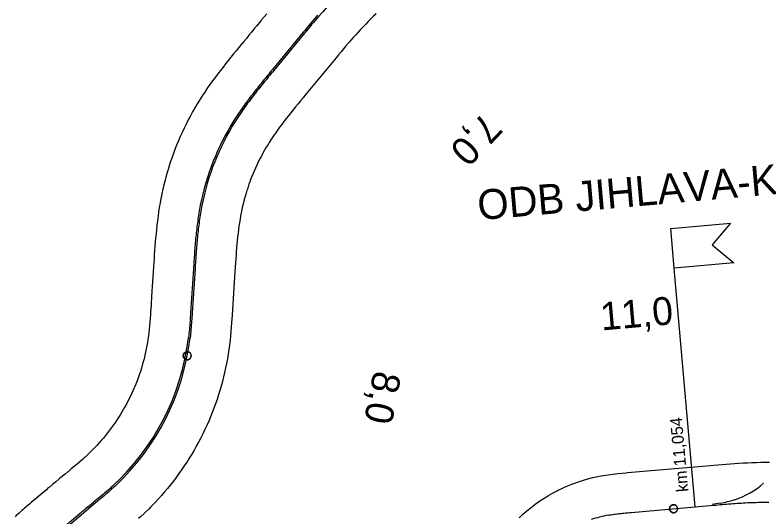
# Model space of a CAD drawing. Extents: x -670810 to -649614, y -1131928 to -1115069.
# Drawn here: x -670180 to -668294, y -1128491 to -1127234 of the extents above; entities that cross this region are included whole.
import ezdxf

# ---------------------------------------------------------------- set-up
doc = ezdxf.new("R2010")
doc.units = 0
for name, color, linetype in [('519 Var SK-4 Praporky stanic', 7, 'Continuous'), ('hranice_VRT_ZUR_Vysocina', 7, 'Continuous'), ('Osa koleje', 7, 'Continuous'), ('Osa koleje úprava GPK', 7, 'Continuous'), ('Situace - Osa koleje 2D', 7, 'Continuous'), ('Staničení - hlavní staničení + kolečka 1k', 7, 'Continuous')]:
    doc.layers.add(name, color=color, linetype=linetype)

# ---------------------------------------------------------------- blocks, each defined once
blk = doc.blocks.new('Sit10Kruh_175')
at = {"layer": 'Staničení - hlavní staničení + kolečka 1k'}
blk.add_lwpolyline([(10, 0), (10, 0.6), (9.9, 1.3), (9.8, 1.9), (9.7, 2.5), (9.5, 3.1), (9.3, 3.7), (9, 4.3), (8.8, 4.8), (8.4, 5.4), (8.1, 5.9), (7.7, 6.4), (7.3, 6.8), (6.8, 7.3), (6.4, 7.7), (5.9, 8.1), (5.4, 8.4), (4.8, 8.8), (4.3, 9), (3.7, 9.3), (3.1, 9.5), (2.5, 9.7), (1.9, 9.8), (1.3, 9.9), (0.6, 10), (0, 10), (-0.6, 10), (-1.3, 9.9), (-1.9, 9.8), (-2.5, 9.7), (-3.1, 9.5), (-3.7, 9.3), (-4.3, 9), (-4.8, 8.8), (-5.4, 8.4), (-5.9, 8.1), (-6.4, 7.7), (-6.8, 7.3), (-7.3, 6.8), (-7.7, 6.4), (-8.1, 5.9), (-8.4, 5.4), (-8.8, 4.8), (-9, 4.3), (-9.3, 3.7), (-9.5, 3.1), (-9.7, 2.5), (-9.8, 1.9), (-9.9, 1.3), (-10, 0.6), (-10, 0), (-10, -0.6), (-9.9, -1.3), (-9.8, -1.9), (-9.7, -2.5), (-9.5, -3.1), (-9.3, -3.7), (-9, -4.3), (-8.8, -4.8), (-8.4, -5.4), (-8.1, -5.9), (-7.7, -6.4), (-7.3, -6.8), (-6.8, -7.3), (-6.4, -7.7), (-5.9, -8.1), (-5.4, -8.4), (-4.8, -8.8), (-4.3, -9), (-3.7, -9.3), (-3.1, -9.5), (-2.5, -9.7), (-1.9, -9.8), (-1.3, -9.9), (-0.6, -10), (0, -10), (0.6, -10), (1.3, -9.9), (1.9, -9.8), (2.5, -9.7), (3.1, -9.5), (3.7, -9.3), (4.3, -9), (4.8, -8.8), (5.4, -8.4), (5.9, -8.1), (6.4, -7.7), (6.8, -7.3), (7.3, -6.8), (7.7, -6.4), (8.1, -5.9), (8.4, -5.4), (8.8, -4.8), (9, -4.3), (9.3, -3.7), (9.5, -3.1), (9.7, -2.5), (9.8, -1.9), (9.9, -1.3)], close=True, dxfattribs=at)
blk.add_circle((0, 0), 10, dxfattribs=at)
blk = doc.blocks.new('Sit10Kruh_177')
at = {"layer": 'Staničení - hlavní staničení + kolečka 1k'}
blk.add_lwpolyline([(10, 0), (10, 0.6), (9.9, 1.3), (9.8, 1.9), (9.7, 2.5), (9.5, 3.1), (9.3, 3.7), (9, 4.3), (8.8, 4.8), (8.4, 5.4), (8.1, 5.9), (7.7, 6.4), (7.3, 6.8), (6.8, 7.3), (6.4, 7.7), (5.9, 8.1), (5.4, 8.4), (4.8, 8.8), (4.3, 9), (3.7, 9.3), (3.1, 9.5), (2.5, 9.7), (1.9, 9.8), (1.3, 9.9), (0.6, 10), (0, 10), (-0.6, 10), (-1.3, 9.9), (-1.9, 9.8), (-2.5, 9.7), (-3.1, 9.5), (-3.7, 9.3), (-4.3, 9), (-4.8, 8.8), (-5.4, 8.4), (-5.9, 8.1), (-6.4, 7.7), (-6.8, 7.3), (-7.3, 6.8), (-7.7, 6.4), (-8.1, 5.9), (-8.4, 5.4), (-8.8, 4.8), (-9, 4.3), (-9.3, 3.7), (-9.5, 3.1), (-9.7, 2.5), (-9.8, 1.9), (-9.9, 1.3), (-10, 0.6), (-10, 0), (-10, -0.6), (-9.9, -1.3), (-9.8, -1.9), (-9.7, -2.5), (-9.5, -3.1), (-9.3, -3.7), (-9, -4.3), (-8.8, -4.8), (-8.4, -5.4), (-8.1, -5.9), (-7.7, -6.4), (-7.3, -6.8), (-6.8, -7.3), (-6.4, -7.7), (-5.9, -8.1), (-5.4, -8.4), (-4.8, -8.8), (-4.3, -9), (-3.7, -9.3), (-3.1, -9.5), (-2.5, -9.7), (-1.9, -9.8), (-1.3, -9.9), (-0.6, -10), (0, -10), (0.6, -10), (1.3, -9.9), (1.9, -9.8), (2.5, -9.7), (3.1, -9.5), (3.7, -9.3), (4.3, -9), (4.8, -8.8), (5.4, -8.4), (5.9, -8.1), (6.4, -7.7), (6.8, -7.3), (7.3, -6.8), (7.7, -6.4), (8.1, -5.9), (8.4, -5.4), (8.8, -4.8), (9, -4.3), (9.3, -3.7), (9.5, -3.1), (9.7, -2.5), (9.8, -1.9), (9.9, -1.3)], close=True, dxfattribs=at)
blk.add_circle((0, 0), 10, dxfattribs=at)
blk = doc.blocks.new('_U709')
at = {"layer": '519 Var SK-4 Praporky stanic'}
blk.add_line((73.8, -456.3), (21.4, 141.2), dxfattribs=at)
blk.add_lwpolyline([(12.7, 240.8), (162.1, 253.9), (116.7, 199.7), (170.8, 154.3), (21.4, 141.2)], close=True, dxfattribs=at)
for s, height, rotation, p in [('ODB JIHLAVA-KALVÁRIE', 75, 5.0106, (-467.5, 261.5)), ('km 11,054', 30, 95.0106, (56.9, -417.8))]:
    blk.add_text(s, height=height, rotation=rotation, dxfattribs=at).set_placement(p)

msp = doc.modelspace()

# ---------------------------------------------------------------- linework, layer by layer
at = {"layer": 'hranice_VRT_ZUR_Vysocina'}
for points in [[(-669550.4, -1127230.9), (-669556.8, -1127238.6), (-669563.1, -1127246.3), (-669564.2, -1127247.5), (-669569.5, -1127254), (-669575.9, -1127261.7), (-669579.8, -1127266.5), (-669582.2, -1127269.4), (-669588.6, -1127277.1), (-669594.9, -1127284.8), (-669601.3, -1127292.6), (-669607.7, -1127300.3), (-669612.9, -1127306.6), (-669614, -1127308), (-669620.5, -1127315.8), (-669626.9, -1127323.6), (-669633.4, -1127331.6), (-669640, -1127339.6), (-669646.5, -1127347.8), (-669653.1, -1127356), (-669659.7, -1127364.4), (-669666.3, -1127372.9), (-669672.9, -1127381.5), (-669679.5, -1127390.3), (-669686.1, -1127399.2), (-669692.6, -1127408.3), (-669699, -1127417.5), (-669705.4, -1127426.9), (-669711.7, -1127436.5), (-669716.9, -1127444.7), (-669718.1, -1127446.5), (-669724, -1127456.1), (-669729.9, -1127466.1), (-669735.7, -1127476.2), (-669741.3, -1127486.4), (-669746.7, -1127496.6), (-669751.9, -1127507), (-669757, -1127517.4), (-669762, -1127527.9), (-669766.7, -1127538.4), (-669770.4, -1127547), (-669771.5, -1127549.4), (-669775.8, -1127559.8), (-669780, -1127570.6), (-669784, -1127581.2), (-669785.3, -1127585), (-669787.9, -1127592.3), (-669789.3, -1127596.4), (-669791.7, -1127603.5), (-669795.2, -1127614.2), (-669796.5, -1127618.5), (-669798.7, -1127625.7), (-669801.8, -1127636.7), (-669804.8, -1127647.9), (-669807.7, -1127659.2), (-669810.3, -1127670.5), (-669812.8, -1127681.7), (-669814.6, -1127690.9), (-669815.1, -1127693.5), (-669817.2, -1127704.5), (-669819.1, -1127715.8), (-669820.8, -1127727), (-669822.4, -1127738.1), (-669823.8, -1127749.1), (-669825.2, -1127760.1), (-669826.3, -1127771), (-669827.4, -1127781.8), (-669828.4, -1127792.4), (-669829.3, -1127803), (-669830.1, -1127813.5), (-669830.9, -1127823.9), (-669831.7, -1127834.3), (-669832.3, -1127844.5), (-669833, -1127854.6), (-669833.6, -1127863.3)], [(-669276.8, -1127230.8), (-669283.4, -1127237.2), (-669289.9, -1127243.7), (-669296.3, -1127250.2), (-669302.7, -1127256.8), (-669309.1, -1127263.4), (-669315.4, -1127270.1), (-669321.6, -1127276.8), (-669327.8, -1127283.6), (-669333.9, -1127290.4), (-669340, -1127297.3), (-669344.3, -1127302.2), (-669345.9, -1127304.1), (-669352.1, -1127311.3), (-669358.1, -1127318.5), (-669364.3, -1127325.9), (-669370.5, -1127333.4), (-669376.8, -1127341), (-669455.7, -1127436.6), (-669459.5, -1127441.2), (-669465.8, -1127448.9), (-669472, -1127456.4), (-669478.1, -1127463.9), (-669484.2, -1127471.4), (-669490.1, -1127478.8), (-669495.9, -1127486.1), (-669501.7, -1127493.4), (-669507.3, -1127500.7), (-669512.8, -1127507.9), (-669518.1, -1127515.1), (-669523.3, -1127522.3), (-669528.4, -1127529.5), (-669533.3, -1127536.6), (-669538.1, -1127543.8), (-669542.8, -1127551.1), (-669544.5, -1127553.7), (-669547.1, -1127557.9), (-669551.5, -1127565.2), (-669555.7, -1127572.5), (-669559.8, -1127579.8), (-669563.8, -1127587.1), (-669567.7, -1127594.6), (-669571.4, -1127602.1), (-669575, -1127609.7), (-669578.5, -1127617.3), (-669581.8, -1127624.8), (-669585.2, -1127632.7), (-669588.3, -1127640.5), (-669591.4, -1127648.5), (-669592.5, -1127651.7), (-669594.2, -1127656.3), (-669594.8, -1127658), (-669596.9, -1127664), (-669599.6, -1127672.4), (-669600.1, -1127673.9), (-669602, -1127680), (-669604.4, -1127688.1), (-669606.6, -1127696.2), (-669608.7, -1127704.3), (-669610.7, -1127712.5), (-669612.5, -1127720.7), (-669614.3, -1127729.2), (-669614.4, -1127729.8), (-669615.8, -1127737.1), (-669617.2, -1127745.6), (-669618.6, -1127754.1), (-669619.9, -1127762.7), (-669621, -1127771.5), (-669622.1, -1127780.3), (-669623.1, -1127789.3), (-669624.1, -1127798.4), (-669624.9, -1127807.6), (-669625.8, -1127816.9), (-669626.5, -1127826.3), (-669627.2, -1127835.8), (-669627.9, -1127845.4), (-669628.6, -1127855.1), (-669629.3, -1127864.9), (-669630, -1127876.3)], [(-669833.6, -1127863.3), (-669833.6, -1127863.3), (-669833.7, -1127864.6), (-669836.9, -1127914.5), (-669837.6, -1127924.5), (-669840.7, -1127973), (-669840.8, -1127974.3), (-669841.4, -1127984.1), (-669842.1, -1127993.7), (-669842.8, -1128003), (-669843.5, -1128012), (-669844.4, -1128020.7), (-669845.3, -1128029.5), (-669845.4, -1128030.2), (-669846.3, -1128037.4), (-669847.5, -1128045.7), (-669848.8, -1128054), (-669850.2, -1128062.2), (-669851.8, -1128070.4), (-669853.5, -1128078.5), (-669855.3, -1128086.6), (-669857.3, -1128094.7), (-669859.4, -1128102.8), (-669861.7, -1128110.8), (-669864, -1128118.8), (-669866.6, -1128126.8), (-669869.2, -1128134.7), (-669872, -1128142.5), (-669874.9, -1128150.3), (-669877.9, -1128158.1), (-669881.2, -1128166), (-669882.7, -1128169.6), (-669884.3, -1128173.2), (-669887.8, -1128181), (-669891.4, -1128188.6), (-669895, -1128196.1), (-669898.8, -1128203.5), (-669902.7, -1128210.8), (-669906.8, -1128218.1), (-669911, -1128225.3), (-669915.2, -1128232.5), (-669919.6, -1128239.6), (-669924.2, -1128246.6), (-669928.8, -1128253.5), (-669933.5, -1128260.3), (-669938.4, -1128267.1), (-669943.4, -1128273.8), (-669948.5, -1128280.4), (-669953.7, -1128286.9), (-669959, -1128293.3), (-669964.4, -1128299.7), (-669970.1, -1128306.2), (-669970.2, -1128306.3), (-669975.5, -1128312), (-669981.3, -1128318.2), (-669985.9, -1128323), (-669986.8, -1128323.9), (-669993, -1128330), (-669999, -1128335.8), (-670004.1, -1128340.5), (-670005.1, -1128341.4), (-670011.4, -1128347.1), (-670018, -1128352.8), (-670024.9, -1128358.7), (-670032, -1128364.7), (-670039.4, -1128370.9), (-670045.6, -1128376), (-670047, -1128377.1), (-670054.8, -1128383.5), (-670068.7, -1128395.1), (-670070.3, -1128396.3), (-670078.2, -1128402.9), (-670086.1, -1128409.5), (-670094, -1128416.1), (-670098.6, -1128420), (-670101.8, -1128422.7), (-670139.9, -1128455), (-670141.2, -1128456.1), (-670141.2, -1128456.1)], [(-669630, -1127876.3), (-669637.1, -1127986.1), (-669637.7, -1127994.7), (-669638.4, -1128005), (-669639.2, -1128015.6), (-669640, -1128026.4), (-669641, -1128037.5), (-669642.2, -1128048.7), (-669642.8, -1128054.3), (-669643.6, -1128060.6), (-669645.1, -1128071.9), (-669646.9, -1128083.5), (-669648.8, -1128094.9), (-669650.9, -1128106.4), (-669653.3, -1128117.8), (-669655.8, -1128129.2), (-669658.5, -1128140.5), (-669661.4, -1128151.8), (-669664.4, -1128163.1), (-669667.7, -1128174.3), (-669671.1, -1128185.4), (-669674.7, -1128196.5), (-669678.6, -1128207.5), (-669682.5, -1128218.5), (-669686.7, -1128229.3), (-669691.1, -1128240.2), (-669695.6, -1128250.9), (-669700.3, -1128261.6), (-669705.2, -1128272.1), (-669710.2, -1128282.6), (-669715.5, -1128293.1), (-669720.9, -1128303.4), (-669726.5, -1128313.6), (-669732.2, -1128323.8), (-669738.1, -1128333.8), (-669744.2, -1128343.8), (-669750.4, -1128353.6), (-669756.8, -1128363.3), (-669763.4, -1128373), (-669770.1, -1128382.5), (-669777, -1128391.9), (-669784, -1128401.2), (-669791.2, -1128410.4), (-669798.5, -1128419.4), (-669806, -1128428.4), (-669813.6, -1128437.2), (-669821.4, -1128445.9), (-669829.3, -1128454.4), (-669837.2, -1128462.7), (-669840.8, -1128466.3), (-669845.7, -1128471.3), (-669853.9, -1128479.3), (-669861.4, -1128486.4), (-669862.5, -1128487.4), (-669866.1, -1128490.7), (-669870.9, -1128495.1)], [(-668919.1, -1128493.2), (-668909.3, -1128484.2), (-668899.3, -1128475.5), (-668888.9, -1128467.1), (-668878.3, -1128459), (-668868.1, -1128451.8), (-668866.6, -1128450.8), (-668856.3, -1128444), (-668845, -1128437.1), (-668833.5, -1128430.6), (-668823.4, -1128425.3), (-668820.9, -1128424), (-668810.1, -1128418.8), (-668805, -1128416.5), (-668797.2, -1128413.1), (-668786.9, -1128408.9), (-668784.4, -1128408), (-668772.6, -1128403.7), (-668759.9, -1128399.5), (-668747.1, -1128395.8), (-668734.3, -1128392.5), (-668721.6, -1128389.7), (-668714.4, -1128388.3), (-668707.9, -1128387.1), (-668695.7, -1128385.2), (-668683.6, -1128383.6), (-668672.1, -1128382.4), (-668661.1, -1128381.3), (-668650.7, -1128380.4), (-668647.3, -1128380.1), (-668440.2, -1128361.9), (-668431.3, -1128361.1), (-668421.2, -1128360.3), (-668411, -1128359.4), (-668400.7, -1128358.5), (-668390.2, -1128357.7), (-668379.7, -1128357), (-668369, -1128356.3), (-668358.2, -1128355.7), (-668347.3, -1128355.1), (-668336.3, -1128354.7), (-668325.2, -1128354.3), (-668314.1, -1128354.1), (-668304.9, -1128354.1), (-668302.4, -1128354.1), (-668292.6, -1128354.2)], [(-670141.2, -1128456.1), (-670144.1, -1128458.6), (-670147.1, -1128461.1), (-670150.2, -1128463.8), (-670153.3, -1128466.5), (-670156.5, -1128469.2), (-670159.8, -1128472.1), (-670163.1, -1128475), (-670166.5, -1128478.1), (-670169.9, -1128481.2), (-670173.4, -1128484.4), (-670176.9, -1128487.7), (-670180, -1128490.8)]]:
    msp.add_lwpolyline(points, dxfattribs=at)
at = {"layer": 'Osa koleje'}
msp.add_line((-668415.6, -1128456.6), (-668436, -1128460.1), dxfattribs=at)
msp.add_arc((-668460.9, -1128193.8), 266.6, 279.7742, 287.8021, dxfattribs=at)
at = {"layer": 'Osa koleje úprava GPK'}
msp.add_arc((-668440.5, -1128257.3), 200, 287.8021, 311.8178, dxfattribs=at)
at = {"layer": 'Situace - Osa koleje 2D'}
for p, q in [((-669459, -1127277.2), (-669535.8, -1127370.3)), ((-669455.8, -1127279.7), (-669532.9, -1127373)), ((-669733.8, -1127869.8), (-669740.9, -1127979.5)), ((-669729.8, -1127869.8), (-669736.9, -1127979.6)), ((-669973.6, -1128451.7), (-670084.9, -1128546)), ((-669998.9, -1128466.9), (-669983.4, -1128454.1)), ((-668638.5, -1128479.7), (-668431.5, -1128461.5)), ((-670017.5, -1128482.4), (-670076.5, -1128532.4))]:
    msp.add_line(p, q, dxfattribs=at)
for points in [[(-669422.9, -1127234.2), (-669427.5, -1127239.5), (-669432, -1127244.8), (-669436.6, -1127250.2), (-669441.1, -1127255.6), (-669445.5, -1127260.9), (-669450, -1127266.3), (-669454.5, -1127271.7), (-669459, -1127277.2)], [(-669419.9, -1127236.7), (-669424.4, -1127242.1), (-669429, -1127247.4), (-669433.5, -1127252.7), (-669438, -1127258.1), (-669442.5, -1127263.5), (-669446.9, -1127268.9), (-669451.4, -1127274.3), (-669455.8, -1127279.7)], [(-669535.8, -1127370.3), (-669539, -1127374.1), (-669542.2, -1127378), (-669545.3, -1127381.9), (-669548.5, -1127385.7), (-669551.7, -1127389.6), (-669554.9, -1127393.5), (-669558.1, -1127397.4), (-669561.2, -1127401.3), (-669564.4, -1127405.2), (-669567.5, -1127409.1), (-669570.7, -1127413), (-669573.8, -1127416.9), (-669576.9, -1127420.8), (-669580, -1127424.8), (-669583.1, -1127428.7), (-669586.2, -1127432.7), (-669589.2, -1127436.7), (-669592.3, -1127440.7), (-669595.3, -1127444.7), (-669598.3, -1127448.7), (-669601.3, -1127452.7), (-669604.3, -1127456.8), (-669607.2, -1127460.8), (-669610.1, -1127464.9), (-669613, -1127469), (-669615.9, -1127473.1), (-669618.7, -1127477.3), (-669621.5, -1127481.4), (-669624.3, -1127485.6), (-669627.1, -1127489.8), (-669629.8, -1127494), (-669632.5, -1127498.2)], [(-669532.9, -1127373), (-669536, -1127376.9), (-669539.2, -1127380.7), (-669542.4, -1127384.6), (-669545.6, -1127388.4), (-669548.7, -1127392.3), (-669551.9, -1127396.2), (-669555.1, -1127400), (-669558.2, -1127403.9), (-669561.4, -1127407.8), (-669564.5, -1127411.7), (-669567.6, -1127415.6), (-669570.8, -1127419.5), (-669573.9, -1127423.4), (-669577, -1127427.4), (-669580, -1127431.3), (-669583.1, -1127435.3), (-669586.1, -1127439.2), (-669589.2, -1127443.2), (-669592.2, -1127447.2), (-669595.2, -1127451.2), (-669598.2, -1127455.2), (-669601.1, -1127459.2), (-669604, -1127463.3), (-669606.9, -1127467.4), (-669609.8, -1127471.4), (-669612.7, -1127475.6), (-669615.5, -1127479.7), (-669618.3, -1127483.8), (-669621.1, -1127488), (-669623.8, -1127492.2), (-669626.5, -1127496.4), (-669629.2, -1127500.6)], [(-669716.5, -1127710.3), (-669717.5, -1127715.3), (-669718.4, -1127720.2), (-669719.3, -1127725.1), (-669720.1, -1127730.1), (-669720.9, -1127735), (-669721.7, -1127740), (-669722.4, -1127744.9), (-669723.1, -1127749.9), (-669723.8, -1127754.9), (-669724.4, -1127759.9), (-669725, -1127764.8), (-669725.6, -1127769.8), (-669726.2, -1127774.8), (-669726.7, -1127779.8), (-669727.2, -1127784.8), (-669727.7, -1127789.8), (-669728.2, -1127794.8), (-669728.7, -1127799.8), (-669729.1, -1127804.8), (-669729.5, -1127809.7), (-669729.9, -1127814.7), (-669730.3, -1127819.7), (-669730.7, -1127824.8), (-669731.1, -1127829.8), (-669731.4, -1127834.8), (-669731.8, -1127839.8), (-669732.1, -1127844.8), (-669732.5, -1127849.8), (-669732.8, -1127854.8), (-669733.1, -1127859.8), (-669733.5, -1127864.8), (-669733.8, -1127869.8)], [(-669712.6, -1127710.8), (-669713.5, -1127715.8), (-669714.4, -1127720.7), (-669715.3, -1127725.6), (-669716.1, -1127730.5), (-669716.9, -1127735.5), (-669717.7, -1127740.4), (-669718.4, -1127745.3), (-669719.1, -1127750.3), (-669719.8, -1127755.3), (-669720.4, -1127760.2), (-669721, -1127765.2), (-669721.6, -1127770.1), (-669722.2, -1127775.1), (-669722.7, -1127780.1), (-669723.2, -1127785), (-669723.7, -1127790), (-669724.2, -1127795), (-669724.7, -1127800), (-669725.1, -1127805), (-669725.5, -1127809.9), (-669725.9, -1127814.9), (-669726.3, -1127819.9), (-669726.7, -1127824.9), (-669727.1, -1127829.9), (-669727.4, -1127834.9), (-669727.8, -1127839.9), (-669728.1, -1127844.8), (-669728.5, -1127849.8), (-669728.8, -1127854.8), (-669729.1, -1127859.8), (-669729.5, -1127864.8), (-669729.8, -1127869.8)], [(-669740.9, -1127979.5), (-669741.3, -1127984.7), (-669741.6, -1127989.9), (-669742, -1127995.2), (-669742.3, -1128000.4), (-669742.7, -1128005.7), (-669743.1, -1128010.9), (-669743.5, -1128016.1), (-669744, -1128021.4), (-669744.5, -1128026.6), (-669745, -1128031.8), (-669745.5, -1128037), (-669746.1, -1128042.2)], [(-669736.9, -1127979.6), (-669737.3, -1127984.9), (-669737.6, -1127990.1), (-669738, -1127995.4), (-669738.3, -1128000.6), (-669738.7, -1128005.9), (-669739.1, -1128011.2), (-669739.5, -1128016.4), (-669740, -1128021.6), (-669740.5, -1128026.9), (-669741, -1128032.1), (-669741.5, -1128037.4), (-669742.1, -1128042.6)], [(-669939.3, -1128416.8), (-669943.3, -1128420.3), (-669947.2, -1128423.8), (-669951.1, -1128427.2), (-669955.1, -1128430.6), (-669959.1, -1128434), (-669963.1, -1128437.4), (-669967.2, -1128440.8), (-669971.2, -1128444.1), (-669975.3, -1128447.5), (-669979.3, -1128450.8), (-669983.4, -1128454.1)], [(-669929.9, -1128413.5), (-669933.8, -1128417.1), (-669937.7, -1128420.7), (-669941.6, -1128424.2), (-669945.6, -1128427.7), (-669949.5, -1128431.2), (-669953.5, -1128434.6), (-669957.5, -1128438.1), (-669961.5, -1128441.5), (-669965.5, -1128444.9), (-669969.5, -1128448.3), (-669973.6, -1128451.7)], [(-668431.5, -1128461.5), (-668426.2, -1128461.1), (-668420.9, -1128460.6), (-668415.6, -1128460.1), (-668410.3, -1128459.7), (-668405.1, -1128459.2), (-668399.8, -1128458.8), (-668394.5, -1128458.4), (-668389.2, -1128458), (-668383.9, -1128457.5), (-668378.6, -1128457.2), (-668373.3, -1128456.8), (-668368, -1128456.4), (-668362.7, -1128456.1), (-668357.4, -1128455.8), (-668352.1, -1128455.5), (-668346.8, -1128455.2), (-668341.5, -1128455), (-668336.2, -1128454.7), (-668330.9, -1128454.5), (-668325.6, -1128454.4), (-668320.3, -1128454.3), (-668315, -1128454.2), (-668309.7, -1128454.1), (-668304.4, -1128454.1), (-668299.1, -1128454.1), (-668293.8, -1128454.2)], [(-668696.1, -1128486.6), (-668692.5, -1128485.9), (-668688.9, -1128485.3), (-668685.4, -1128484.8), (-668681.8, -1128484.3), (-668678.2, -1128483.8), (-668674.6, -1128483.3), (-668671, -1128482.9), (-668667.4, -1128482.4), (-668663.8, -1128482), (-668660.2, -1128481.7), (-668656.6, -1128481.3), (-668653, -1128481), (-668649.3, -1128480.6), (-668645.7, -1128480.3), (-668642.1, -1128480), (-668638.5, -1128479.7)]]:
    msp.add_lwpolyline(points, dxfattribs=at)
for centre, radius, start, end in [((-668504.6, -1128028.2), 1210, 128.2319, 139.1479), ((-669104.2, -1127830.4), 624, 147.843, 168.9094), ((-669104.2, -1127830.4), 620, 147.8668, 168.8857), ((-670342, -1127971.9), 600, 312.1486, 353.2707), ((-670342, -1127971.9), 604, 313.0177, 353.2806), ((-668983.4, -1129703.3), 1600, 129.3991, 130.2667), ((-668641, -1128783.5), 302, 100.5125, 108.8552)]:
    msp.add_arc(centre, radius, start, end, dxfattribs=at)

# ---------------------------------------------------------------- block references
at = {"layer": '519 Var SK-4 Praporky stanic'}
msp.add_blockref('_U709', (-668552.2, -1128009.3), dxfattribs=at)
at = {"layer": 'Staničení - hlavní staničení + kolečka 1k'}
for name, p, rotation in [('Sit10Kruh_175', (-669749.1, -1128087.3), -101.01126100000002), ('Sit10Kruh_177', (-668532.2, -1128470.4), 5.010579)]:
    msp.add_blockref(name, p, dxfattribs=dict(at, rotation=rotation))

# ---------------------------------------------------------------- texts
for s, rotation, p in [('7,0', 226.4477, (-669006.7, -1127475)), ('11,0', 5.0106, (-668712.6, -1128024.1)), ('8,0', 258.9887, (-669282.2, -1128122.1))]:
    msp.add_text(s, height=70, rotation=rotation, dxfattribs=at).set_placement(p)

doc.saveas('drawing.dxf')
